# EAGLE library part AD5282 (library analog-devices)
Dual +15 V/±5 V, 256-Position, I2C-Compatible Digital Potentiometer Source: http://www.analog.com/static/imported-files/data_sheets/AD5280_5282.pdf
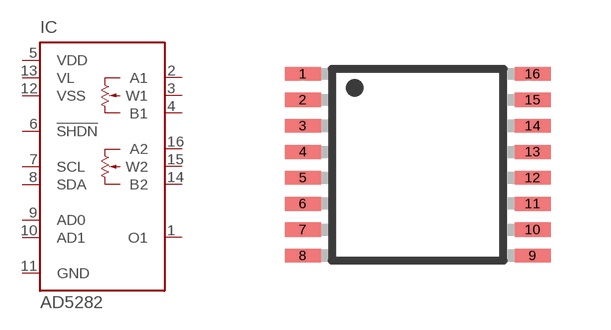
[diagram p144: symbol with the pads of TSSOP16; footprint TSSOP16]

Designator prefix IC

## AD5282 (MF: ALTERA CORPORATION; MPN: AD5282BRUZ50; OC_FARNELL: 1438442; OC_NEWARK: 59K3850)  [TSSOP16]
1  O1  out
2  A1  pas
3  W1  pas
4  B1  pas
5  VDD  pwr
6  !SHDN  in
7  SCL  in
8  SDA
9  AD0  in
10  AD1  in
11  GND  pwr
12  VSS  pwr
13  VL  pwr
14  B2  pas
15  W2  pas
16  A2  pas

## Footprint TSSOP16 (pad centres in mm)
16-Lead Thin Shrink Small Outline Package [TSSOP] (RU-16) Source: 8x ADG1408_1409.pdf
smd 0.9 x 0.35: 1 -2.875,2.275; 2 -2.875,1.625; 3 -2.875,0.975; 4 -2.875,0.325; 5 -2.875,-0.325; 6 -2.875,-0.975; 7 -2.875,-1.625; 8 -2.875,-2.275; 9 2.875,-2.275; 10 2.875,-1.625; 11 2.875,-0.975; 12 2.875,-0.325; 13 2.875,0.325; 14 2.875,0.975; 15 2.875,1.625; 16 2.875,2.275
